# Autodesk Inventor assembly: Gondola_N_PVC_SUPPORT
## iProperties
Shininess: 64.0
Length Units: 11272
Angle Units: 11279
Time Units: 11290
Mass Units: 11286
Length Display Precision: 3
Angle Display Precision: 2
Compacted: True
Part Number: Gondola_N_PVC_SUPPORT
Document SubType Name: Assembly
Created: 2004-12
Designer: John Blackburn
Manufacturer: Standard
Standards Organization: Custom
Density: 0.0
Volumn: 0.0
Area: 0.0
PropertySet Name: Model Information
Control State: 0
Master: False
Checked Out: False
Author: John Blackburn
